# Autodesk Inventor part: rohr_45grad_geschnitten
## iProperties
Author: R.Lampe
Created: 2002-09
Part Number: rohr_45grad_geschnitten
Project: Support
Material: Stahl (schweißbar)
Document SubType Name: Modellieren
Designer: R.Lampe
Category: Support
Company: alltrotec GmbH
Control State: 0
Master: False
Checked Out: False
PropertySet Name: Design Tracking Control
Shininess: 20.0
Angle Display Precision: 2
Document Length Units: 11269
Document Angle Units: 11283
Document Time Units: 11279
Document Mass Units: 11290
Document Length Units Precision: 3
Document Angle Units Precision: 2
Compacted: False
PropertySet Name: _Private Model Information
Density: 0.0
Volumn: 0.0
Area: 0.0
PropertySet Name: Model Information
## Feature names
1. Extrusion1
2. Bohrung1 [Hole]
3. Bohrung2 [Hole]
